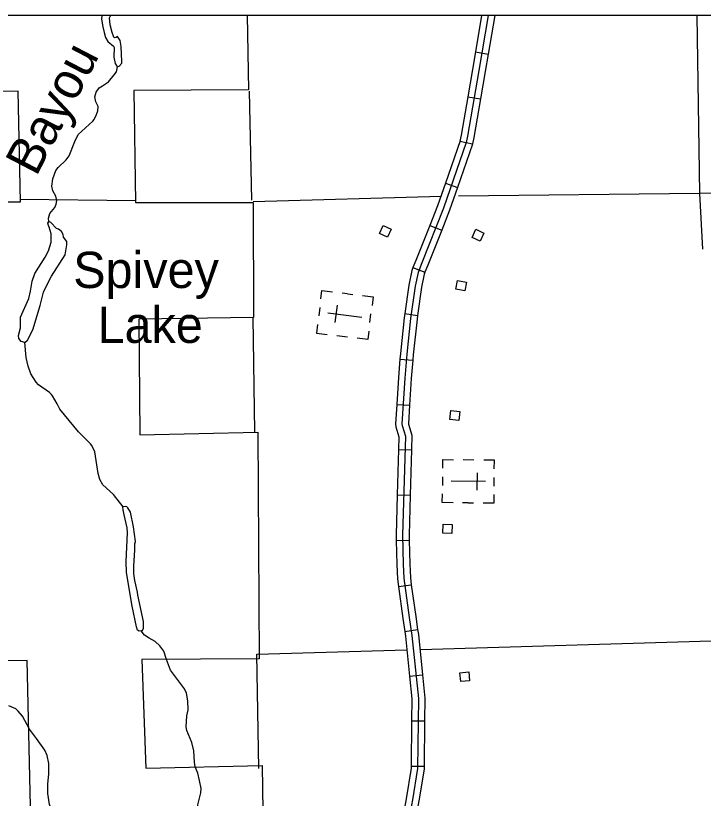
# Model space of a CAD drawing. Extents: x 1084508 to 1142749, y 1057638 to 1093403.
# Drawn here: x 1099802 to 1102314, y 1090543 to 1093403 of the extents above; entities that cross this region are included whole.
import ezdxf

# ---------------------------------------------------------------- set-up
doc = ezdxf.new("R2010")
doc.units = 0
for name, color, linetype in [('DSN_DRFT_Named-Boundary', 7, 'Continuous'), ('Level 32', 7, 'Continuous'), ('Level 35', 7, 'Continuous'), ('Level 5', 7, 'Continuous'), ('Level 56', 7, 'Continuous'), ('Level 57', 7, 'Continuous'), ('Level 7', 7, 'Continuous')]:
    doc.layers.add(name, color=color, linetype=linetype)

msp = doc.modelspace()

# ---------------------------------------------------------------- linework, layer by layer
at = {"layer": 'DSN_DRFT_Named-Boundary'}
msp.add_lwpolyline([(1084507.9, 1057640), (1142749.2, 1057640), (1142749.2, 1093403.4), (1084507.9, 1093403.4)], close=True, dxfattribs=at)
at = {"layer": 'Level 32'}
for p, q in [((1101504.3, 1093403.4), (1101481.4, 1093270.6)), ((1101528.2, 1093403.4), (1101493.7, 1093202.7)), ((1101552, 1093403.4), (1101527.8, 1093262.6)), ((1101481.4, 1093270.6), (1101527.8, 1093262.6)), ((1101453.6, 1093107.1), (1101500, 1093099.3)), ((1101425.2, 1092944.7), (1101471.4, 1092935.2)), ((1101371.9, 1092791), (1101416.4, 1092775.6)), ((1101314.7, 1092636.7), (1101358.4, 1092619.3)), ((1101253.4, 1092482.5), (1101297.3, 1092465.4)), ((1101223.5, 1092314.2), (1101270.1, 1092307.8)), ((1101205.8, 1092148.2), (1101252.7, 1092144.2)), ((1101194.1, 1091982.3), (1101241.1, 1091979.5)), ((1101200.6, 1091817.7), (1101247.7, 1091816.4)), ((1101196.1, 1091652.1), (1101243.1, 1091650.8)), ((1101192.4, 1091485.2), (1101239.5, 1091486.3)), ((1101200.7, 1091317.1), (1101247.4, 1091323.5)), ((1101223.7, 1091152.8), (1101270.3, 1091159.6)), ((1101241.1, 1090989.1), (1101287.9, 1090993.8)), ((1101248.6, 1090826.4), (1101295.7, 1090825.9)), ((1101247, 1090660.6), (1101294.1, 1090660.2))]:
    msp.add_line(p, q, dxfattribs=at)
for points in [[(1101481.4, 1093270.6), (1101470.5, 1093206.7), (1101453.6, 1093107.1)], [(1101527.8, 1093262.6), (1101516.9, 1093198.7), (1101500, 1093099.3)], [(1101493.7, 1093202.7), (1101452.9, 1092962.4), (1101448.2, 1092939.5), (1101365.4, 1092700.3), (1101285.6, 1092500.3), (1101271.8, 1092464.8), (1101261.1, 1092414.5)], [(1101453.6, 1093107.1), (1101429.8, 1092966.8), (1101425.2, 1092944.7)], [(1101500, 1093099.3), (1101476, 1092958.1), (1101471.4, 1092935.2)], [(1101425.5, 1092945.7), (1101371.9, 1092791)], [(1101471.4, 1092935.2), (1101471, 1092933.3), (1101416.4, 1092775.6)], [(1101371.9, 1092791), (1101343.3, 1092708.5), (1101314.7, 1092636.7)], [(1101416.4, 1092775.6), (1101387.4, 1092692.1), (1101358.4, 1092619.3)], [(1101314.7, 1092636.7), (1101263.7, 1092509), (1101253.4, 1092482.5)], [(1101358.4, 1092619.3), (1101307.5, 1092491.7), (1101297.3, 1092465.4)], [(1101253.4, 1092482.5), (1101249.1, 1092471.6), (1101237.9, 1092418.6), (1101223.5, 1092314.2)], [(1101297.3, 1092465.4), (1101294.4, 1092458.1), (1101284.3, 1092410.5), (1101270.1, 1092307.8)], [(1101261.1, 1092414.5), (1101244.8, 1092296.6), (1101230.9, 1092166.1), (1101223.5, 1092078.8), (1101213.3, 1091911.3), (1101213.9, 1091905.3), (1101225.6, 1091866.7), (1101215.5, 1091504), (1101218.1, 1091398.3), (1101220.3, 1091347.4), (1101240.1, 1091203.8), (1101249.7, 1091138), (1101273, 1090907.5), (1101270.5, 1090651.2), (1101251.2, 1090537.4), (1101241.3, 1090479), (1101234.4, 1090432), (1101216.5, 1090208.1), (1101216.9, 1090201.4)], [(1101223.5, 1092314.2), (1101221.5, 1092299.4), (1101207.5, 1092168.4), (1101205.8, 1092148.2)], [(1101270.1, 1092307.8), (1101268.2, 1092293.7), (1101254.4, 1092163.9), (1101252.7, 1092144.2)], [(1101205.8, 1092148.2), (1101200, 1092080.5), (1101194.1, 1091982.3)], [(1101252.7, 1092144.2), (1101247, 1092077.1), (1101241.1, 1091979.5)], [(1101194.1, 1091982.3), (1101189.7, 1091910.9), (1101190.7, 1091900.7), (1101201.9, 1091863.5), (1101200.6, 1091817.7)], [(1101241.1, 1091979.5), (1101236.9, 1091911.6), (1101237.1, 1091909.8), (1101249.2, 1091869.8), (1101247.7, 1091816.4)], [(1101200.6, 1091817.7), (1101196.1, 1091652.1)], [(1101247.7, 1091816.4), (1101243.1, 1091650.8)], [(1101196.1, 1091652.1), (1101191.9, 1091504), (1101192.4, 1091485.2)], [(1101243.1, 1091650.8), (1101239, 1091503.9), (1101239.5, 1091486.3)], [(1101192.4, 1091485.2), (1101194.6, 1091397.5), (1101196.9, 1091345.3), (1101200.7, 1091317.1)], [(1101239.5, 1091486.3), (1101241.7, 1091399.1), (1101243.8, 1091349.6), (1101247.4, 1091323.5)], [(1101200.7, 1091317.1), (1101216.7, 1091200.5), (1101223.7, 1091152.8)], [(1101247.4, 1091323.5), (1101263.4, 1091207.1), (1101270.3, 1091159.6)], [(1101223.7, 1091152.8), (1101226.3, 1091135.1), (1101241.1, 1090989.1)], [(1101270.3, 1091159.6), (1101273, 1091140.9), (1101287.9, 1090993.8)], [(1101241.1, 1090989.1), (1101249.4, 1090906.4), (1101248.6, 1090826.4)], [(1101287.9, 1090993.8), (1101296.5, 1090908.6), (1101295.7, 1090825.9)], [(1101248.6, 1090826.4), (1101247, 1090660.6)], [(1101295.7, 1090825.9), (1101294.1, 1090660.2)], [(1101247, 1090660.6), (1101247, 1090653.3), (1101228, 1090541.3), (1101221.2, 1090500.8)], [(1101294.1, 1090660.2), (1101294, 1090649.2), (1101274.5, 1090533.5), (1101267.6, 1090492.9)]]:
    msp.add_lwpolyline(points, dxfattribs=at)
at = {"layer": 'Level 35'}
for points in [[(1100117, 1093403.4), (1100115.7, 1093390.8), (1100120.6, 1093362.7), (1100125.6, 1093342.1)], [(1100161.8, 1093187.1), (1100169.9, 1093198.2), (1100173.6, 1093216.3), (1100180.4, 1093219.1), (1100189.4, 1093230.2), (1100190.4, 1093235.3), (1100187.2, 1093290.3), (1100183.5, 1093312.5), (1100173.5, 1093326.6), (1100168.8, 1093323.9), (1100162.9, 1093322.7), (1100160.6, 1093325.2), (1100153.9, 1093341.9), (1100146.8, 1093369.4), (1100144.5, 1093394.8), (1100148.3, 1093402.2), (1100149.7, 1093403.4)], [(1100125.6, 1093342.1), (1100129.8, 1093323.3), (1100138.3, 1093308.8), (1100159.4, 1093292), (1100161.2, 1093287.4), (1100160.4, 1093252), (1100165.2, 1093228.2), (1100171.6, 1093218.4)], [(1100173.6, 1093216.3), (1100171.6, 1093218.4)], [(1099924.7, 1092629.9), (1099921.6, 1092636.4), (1099919.7, 1092644.8), (1099922.9, 1092650.6), (1099921.4, 1092663.5), (1099926.7, 1092680.7), (1099944.7, 1092702.6), (1099950.5, 1092714.8), (1099952.8, 1092727.8), (1099948.4, 1092743.4), (1099937.2, 1092763.1), (1099934, 1092780.6), (1099937.9, 1092807), (1099948.3, 1092837.7), (1099957, 1092848.7), (1099986.8, 1092875.8), (1099997.5, 1092890.7), (1100017.7, 1092943.9), (1100029.9, 1092968.6), (1100084, 1093017.8), (1100088.8, 1093023.7), (1100097.8, 1093042), (1100102, 1093055.1), (1100102.9, 1093070.9), (1100094.6, 1093088.9), (1100091.1, 1093106.7), (1100096, 1093123.9), (1100106.4, 1093139.8), (1100119.7, 1093147), (1100141.7, 1093162), (1100161.8, 1093187.1)], [(1099932.4, 1092018.1), (1099926.1, 1092025.5), (1099885.2, 1092054.1), (1099876.3, 1092063.8), (1099857.8, 1092093.6), (1099847.5, 1092122.6), (1099840.8, 1092153.8), (1099835.5, 1092208.5), (1099822.4, 1092212.7), (1099813.8, 1092223), (1099812.3, 1092234.3), (1099819.7, 1092262.1), (1099820, 1092300.9), (1099850.3, 1092369.2), (1099856.5, 1092396), (1099862.8, 1092433.1), (1099872.4, 1092460.6), (1099910.3, 1092520.8), (1099922.3, 1092543.4), (1099932, 1092575), (1099931.1, 1092605.5), (1099924.7, 1092629.9)], [(1099835.5, 1092208.5), (1099845.2, 1092216.7), (1099864.7, 1092255.1), (1099892, 1092344.4), (1099904.2, 1092392.2), (1099911.6, 1092411.1), (1099933.3, 1092451.7), (1099983.3, 1092529.4), (1099988.8, 1092565.6), (1099988.6, 1092577.9), (1099976.9, 1092593.8), (1099975.9, 1092603.2), (1099969.7, 1092615), (1099958.7, 1092622.7), (1099951, 1092625.6), (1099930.6, 1092646.8), (1099925.1, 1092650.1)], [(1099925.1, 1092650.1), (1099922.9, 1092650.6)], [(1100260.4, 1091154.5), (1100253.2, 1091153.6), (1100247.3, 1091157.8), (1100243.1, 1091169.9), (1100228, 1091244.6), (1100206.6, 1091368.3), (1100205.3, 1091408.3), (1100210.5, 1091512.9), (1100209.1, 1091530.8), (1100198.9, 1091579.3), (1100194.7, 1091597.4), (1100194, 1091606.8), (1100195.2, 1091608.4), (1100159.7, 1091653), (1100119.8, 1091688), (1100109.9, 1091707.5), (1100103.3, 1091729.3), (1100091.2, 1091808.6), (1100079.9, 1091832.7), (1100075.2, 1091838.8), (1100030.9, 1091881.8), (1099962.9, 1091964.8), (1099953, 1091984), (1099936.4, 1092013.6), (1099932.4, 1092018.1)], [(1100203.4, 1091609.3), (1100195.2, 1091608.4)], [(1100260.4, 1091154.5), (1100265.3, 1091156.6), (1100269.1, 1091164), (1100268.4, 1091189.5), (1100247.8, 1091285.5), (1100247, 1091296.2), (1100237.7, 1091338.7), (1100233.9, 1091363.8), (1100233.3, 1091392.7), (1100237.6, 1091449.7), (1100237.9, 1091472.7), (1100239.4, 1091481.9), (1100232.2, 1091535.5), (1100220.9, 1091589), (1100212.1, 1091604.1), (1100207.8, 1091608), (1100203.4, 1091609.3)], [(1100352.9, 1091049.8), (1100342.8, 1091080.6), (1100328.1, 1091100.2), (1100311.1, 1091115.9), (1100289.8, 1091128), (1100272.7, 1091139.6), (1100260.4, 1091154.5)], [(1100471.9, 1090451.1), (1100467.1, 1090460), (1100464.4, 1090473.2), (1100467.9, 1090518.7), (1100479, 1090563), (1100479.3, 1090578.8), (1100474, 1090607.2), (1100466.9, 1090634.4), (1100458.1, 1090657.7), (1100455.5, 1090674.9), (1100452.5, 1090716.1), (1100446, 1090746.1), (1100427.1, 1090790.4), (1100424.4, 1090803.9), (1100427.8, 1090844.1), (1100432.2, 1090865.7), (1100431.2, 1090898.4), (1100426, 1090926.6), (1100418.4, 1090943.3), (1100367.1, 1091011.6), (1100352.9, 1091049.8)], [(1100017.7, 1090402.5), (1099997.9, 1090425), (1099970.8, 1090447.6), (1099949.3, 1090471.9), (1099935, 1090498.1), (1099925, 1090520.4), (1099918.9, 1090560.2), (1099919.4, 1090594.3), (1099922.6, 1090632.6), (1099922.6, 1090669.8), (1099917.6, 1090698.9), (1099909, 1090718.4), (1099878.6, 1090761.4), (1099852, 1090795.6), (1099827.4, 1090842.8), (1099811.5, 1090860.8), (1099802, 1090869.3), (1099776.4, 1090880.2)]]:
    msp.add_lwpolyline(points, dxfattribs=at)
at = {"layer": 'Level 5'}
for points in [[(1102290.5, 1093403.4), (1102300.1, 1092753.5), (1102311.1, 1092550.4)], [(1100664.6, 1092728.5), (1100656.6, 1093127.9)], [(1103450, 1092779.5), (1103063.2, 1092775.1), (1102300.1, 1092753.5), (1101419.4, 1092743.3)], [(1101357.9, 1092742.2), (1100670.1, 1092723.3)], [(1100240.1, 1092727.1), (1099819.5, 1092731.1)], [(1100675.1, 1091881.8), (1100669.9, 1092300.6)], [(1101281.1, 1091086.9), (1102344.6, 1091118.5), (1102568.1, 1091114.3)], [(1100682.6, 1091069.1), (1101230.6, 1091085.4)], [(1100690, 1090651.8), (1100682.6, 1091069.1)]]:
    msp.add_lwpolyline(points, dxfattribs=at)
at = {"layer": 'Level 56'}
for points in [[(1101144.1, 1092636.9), (1101173.9, 1092623.4), (1101160.3, 1092593.6), (1101130.6, 1092607.1)], [(1101499.1, 1092578.9), (1101469.4, 1092592.6), (1101483.2, 1092622.4), (1101512.8, 1092608.6)], [(1101410.5, 1092403.3), (1101416.6, 1092435.3), (1101448.8, 1092429.2), (1101442.6, 1092397.1)], [(1101388.4, 1091927.6), (1101392.2, 1091960), (1101424.7, 1091956.2), (1101420.9, 1091923.7)], [(1101395.4, 1091510.8), (1101362.7, 1091511.9), (1101363.8, 1091544.7), (1101396.5, 1091543.6)], [(1101427.7, 1090969.1), (1101424.5, 1091001.6), (1101457.1, 1091004.8), (1101460.3, 1090972.2)]]:
    msp.add_lwpolyline(points, close=True, dxfattribs=at)
at = {"layer": 'Level 57'}
for p, q in [((1101014.4, 1092387.1), (1100995.2, 1092389.5)), ((1101014.4, 1092387.1), (1101034.1, 1092384.5)), ((1100969.3, 1092282.1), (1100977.3, 1092344.6)), ((1100913, 1092336.9), (1100909.1, 1092305.7)), ((1100942.2, 1092317.2), (1101066.7, 1092301.3)), ((1101095.9, 1092281.9), (1101099.9, 1092313)), ((1101004.4, 1092309.2), (1101004.4, 1092309.2)), ((1101004.4, 1092309.2), (1101004.4, 1092309.2)), ((1100975.3, 1092233.8), (1101014.2, 1092228.9)), ((1101476.1, 1091779.2), (1101436.9, 1091779.7)), ((1101361.8, 1091717.7), (1101361.4, 1091686.3)), ((1101487.6, 1091732), (1101486.8, 1091668.9)), ((1101549.8, 1091683.9), (1101550.2, 1091715.3)), ((1101518.6, 1091700.2), (1101393, 1091701.8)), ((1101455.8, 1091701), (1101455.8, 1091701)), ((1101455.8, 1091701), (1101455.8, 1091701)), ((1101454.8, 1091622.5), (1101434.9, 1091622.8)), ((1101454.8, 1091622.5), (1101474.1, 1091622.3))]:
    msp.add_line(p, q, dxfattribs=at)
for points in [[(1100917, 1092367.8), (1100921, 1092399), (1100959.9, 1092394)], [(1101068.9, 1092380.1), (1101107.8, 1092375.1), (1101103.8, 1092344)], [(1100905.1, 1092274.4), (1100901.1, 1092243.3), (1100940, 1092238.3)], [(1101091.9, 1092250.6), (1101087.9, 1092219.5), (1101049, 1092224.4)], [(1101362.2, 1091749.3), (1101362.6, 1091780.7), (1101401.9, 1091780.2)], [(1101550.6, 1091746.9), (1101551, 1091778.3), (1101511.7, 1091778.8)], [(1101399.9, 1091623.2), (1101360.6, 1091623.7), (1101361, 1091655.1)], [(1101549.4, 1091652.7), (1101549, 1091621.3), (1101509.7, 1091621.8)]]:
    msp.add_lwpolyline(points, dxfattribs=at)
at = {"layer": 'Level 7'}
for points in [[(1100720.9, 1089394.6), (1100298.4, 1089388.5), (1100289.6, 1089826.9), (1099872.5, 1089819.4), (1099844.5, 1091046.8), (1099410, 1091044), (1099384.5, 1092722.9), (1099819.1, 1092722.7), (1099811, 1093127.3), (1099600.9, 1093126.3), (1099595.3, 1093403.4)], [(1100648, 1093403.4), (1100652, 1093132.4), (1100233.4, 1093129.3), (1100240.2, 1092720.1), (1100669.7, 1092720.7), (1100671.1, 1092300.1), (1100252.2, 1092294.6), (1100255.8, 1091871.6), (1100686.4, 1091880.6), (1100691.6, 1091052.4), (1100263.1, 1091049.6), (1100277.3, 1090652.6), (1100702.2, 1090662.5), (1100719.3, 1089497.3)]]:
    msp.add_lwpolyline(points, dxfattribs=at)

# ---------------------------------------------------------------- texts
at = {"layer": 'Level 35'}
msp.add_text('Bayou', height=132.58, rotation=62.5074, dxfattribs=at).set_placement((1099876.9, 1092812.3))
for s, p in [('Spivey', (1100012.1, 1092407.9)), ('Lake', (1100101.1, 1092207.3))]:
    msp.add_text(s, height=132.58, dxfattribs=at).set_placement(p)

doc.saveas('drawing.dxf')
